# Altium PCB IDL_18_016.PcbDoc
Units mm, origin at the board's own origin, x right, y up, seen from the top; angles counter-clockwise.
Board outline 60 x 33 mm, 2 copper layers (Top Layer, Bottom Layer), stack 1.568 mm thick; 47 components, 22 nets, 136 pads, 21 vias.
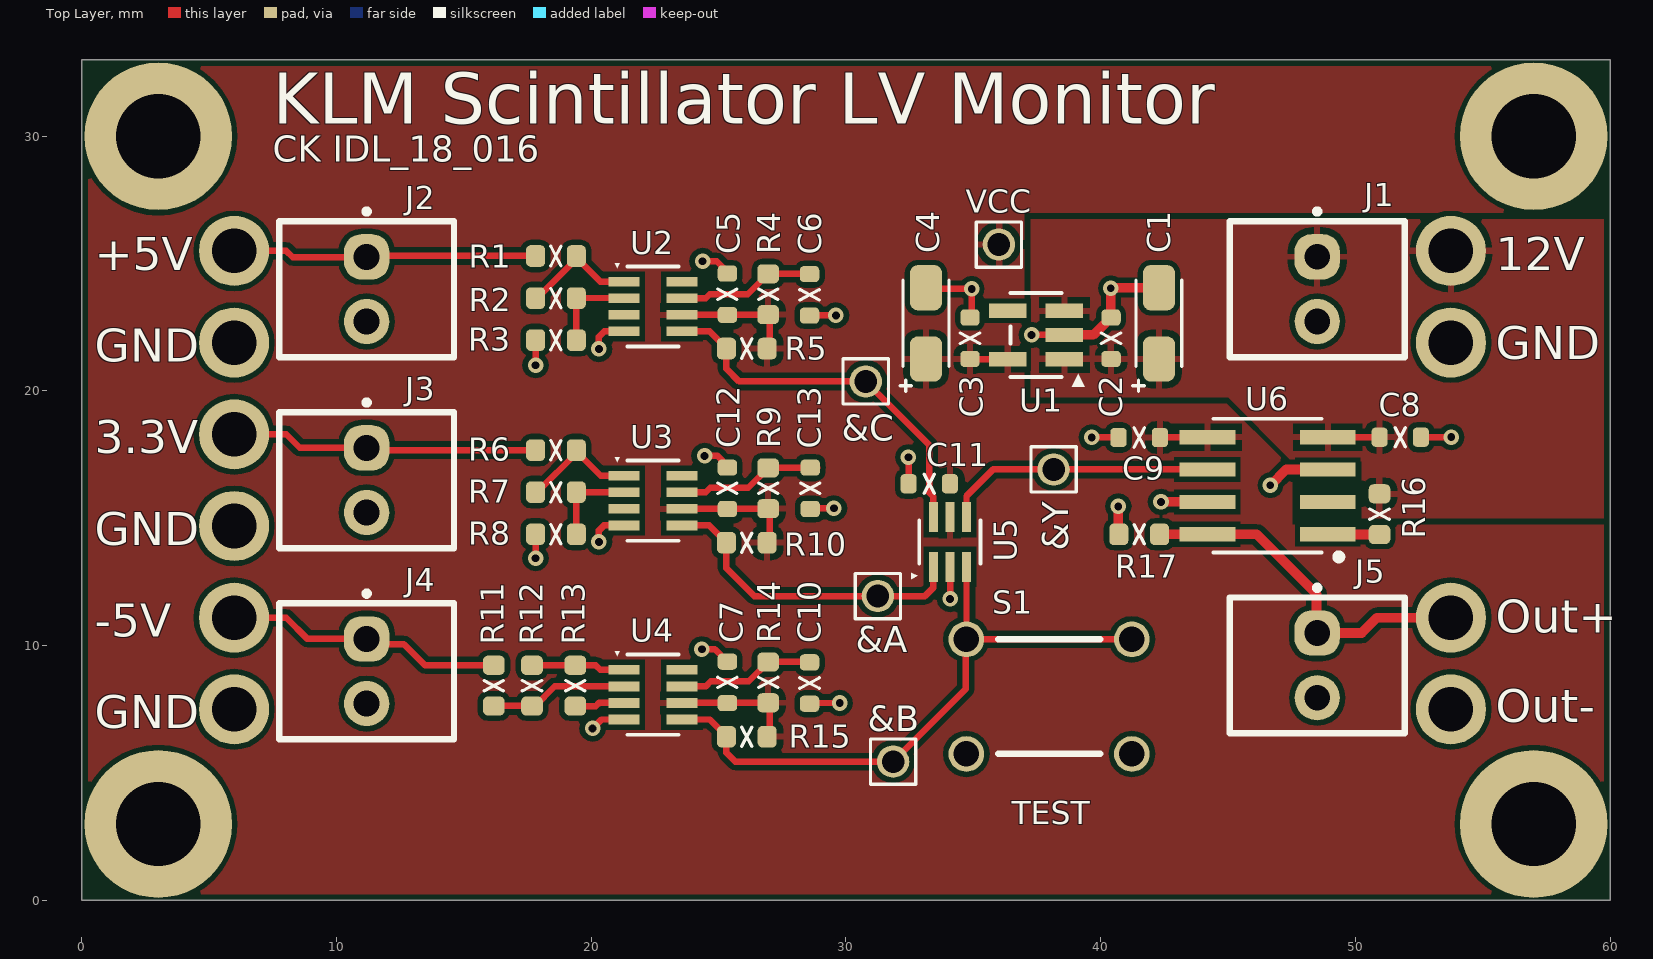
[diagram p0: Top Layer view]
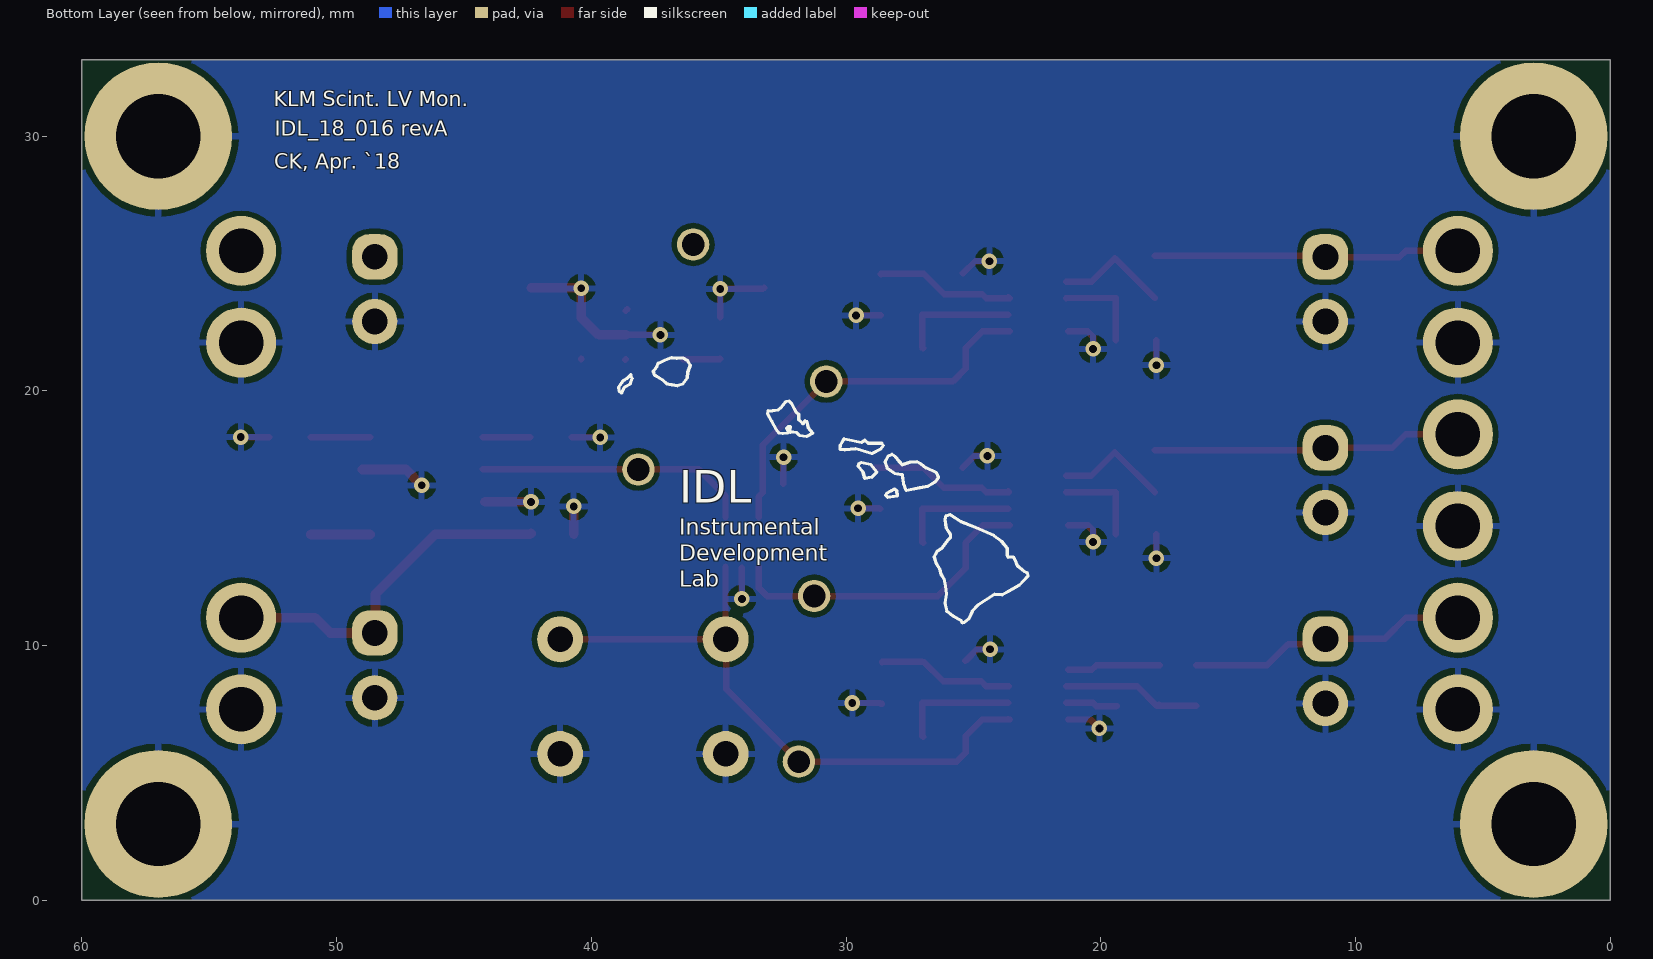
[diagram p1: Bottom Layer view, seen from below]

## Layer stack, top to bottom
Top Solder: solder mask 0.0102, Solder Resist, Dk 3.5
Top Layer: signal copper 0.0348
Dielectric 1: core 1.4986, FR-4, Dk 4.2
Bottom Layer: signal copper 0.0348
Bottom Solder: solder mask 0.0102, Solder Resist, Dk 3.5

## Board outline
0,0 0,33 60,33 60,0

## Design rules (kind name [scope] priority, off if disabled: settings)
Clearance [All] p1: gap=0.203 ignorepadtopadclearanceinfootprint=FALSE
HoleSize [All] p1: absolutevalues=TRUE maxlimit=5.5 minlimit=0.025 maxpercent=80.000 minpercent=20.000
MinimumSolderMaskSliver [All] p1: minsoldermaskwidth=0.102
PolygonConnect [All] p1: connectstyle=Relief reliefconductorwidth=0.254 reliefentries=4 polygonreliefangle="90 Angle" airgapwidth=0.254
RoutingVias [All] p1: holewidth=0.305 width=0.61 viastyle="Through Hole" minholewidth=0.305 minwidth=0.61 maxholewidth=0.762 maxwidth=1.524
SilkToSilkClearance [All] p1: silktosilkclearance=0.127
SilkToSolderMaskClearance [IsPad] p1: minsilkscreentomaskgap=0.127 clearancetoexposedcopper=TRUE
SolderMaskExpansion [All] p1: expansion=0.051
Width [All] p1: maxlimit=1.016 minlimit=0.254 preferedwidth=0.254
26 further rules are at their usual default settings.

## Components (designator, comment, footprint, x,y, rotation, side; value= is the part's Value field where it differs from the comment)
&A "testpoint" testpoint 31.25,11.95 r0 top
&B "testpoint" testpoint 31.85,5.45 r270 top
&C "testpoint" testpoint 30.775,20.375 r0 top
&Y "testpoint" testpoint 38.151,16.92 r0 top (schematic designator &out)
C1 "1uF" CTC-A3216-18 42.286,22.657 r90 top
C2 "100nF" CC0603RF1R 40.406,22.073 r270 top
C3 "100nF" CC0603RF1R 34.869,22.073 r270 top
C4 "2.2uF" CTC-A3216-18 33.142,22.657 r90 top
C5 "100nF" CC0603RF1R 25.344,23.8 r270 top
C6 "Do Not Install" CC0603RF1R 28.57,23.774 r90 top
C7 "100nF" CC0603RF1R 25.344,8.56 r270 top
C8 "100nF" CC0603RF1R 51.76,18.187 r180 top
C9 "100nF" CC0603RF1R 41.511,18.174 r180 top
C10 "Do Not Install" CC0603RF1R 28.57,8.534 r90 top
C11 "100nF" CC0603RF1R 33.269,16.358 r0 top
C12 "100nF" CC0603RF1R 25.344,16.18 r270 top
C13 "Do Not Install" CC0603RF1R 28.595,16.18 r90 top
J1 "Molex 22-23-2021" 32_MMBX-50-0-4 48.5,24 r270 top
J2 "Molex 22-23-2021" 32_MMBX-50-0-4 11.182,23.997 r270 top
J3 "Molex 22-23-2021" 32_MMBX-50-0-4 11.182,16.497 r270 top (schematic designator J4)
J4 "Molex 22-23-2021" 32_MMBX-50-0-4 11.182,8.997 r270 top (schematic designator J3)
J5 "Molex 22-23-2021" 32_MMBX-50-0-4 48.5,9.225 r270 top
R1 "100k" RC0603N1R 18.613,25.298 r180 top (schematic designator R2)
R2 "2.61k" RC0603N1R 18.613,23.647 r180 top (schematic designator R3)
R3 "10k" RC0603N1R 18.613,21.996 r0 top (schematic designator R5)
R4 "0" RC0603N1R 26.944,23.8 r270 top (schematic designator R1)
R5 "100k" RC0603N1R 26.106,21.666 r0 top (schematic designator R4)
R6 "61.9k" RC0603N1R 18.613,17.678 r180 top (schematic designator R14)
R7 "2.61k" RC0603N1R 18.613,16.027 r180 top (schematic designator R15)
R8 "10k" RC0603N1R 18.613,14.376 r0 top (schematic designator R17)
R9 "0" RC0603N1R 26.944,16.18 r270 top (schematic designator R13)
R10 "100k" RC0603N1R 26.106,14.046 r0 top (schematic designator R16)
R11 "121k" RC0603N1R 16.174,8.433 r90 top (schematic designator R7)
R12 "2.1k" RC0603N1R 17.673,8.433 r90 top (schematic designator R8)
R13 "10k" RC0603N1R 19.375,8.433 r270 top (schematic designator R12)
R14 "0" RC0603N1R 26.944,8.56 r270 top (schematic designator R6)
R15 "100k" RC0603N1R 26.106,6.426 r0 top (schematic designator R10)
R16 "3.74k" RC0603N1R 50.947,15.164 r270 top (schematic designator R9)
R17 "4.99k" RC0603N1R 41.511,14.374 r0 top (schematic designator R11)
S1 "B3F-1052" B3F-1052 37.975,8 r180 top
U1 "TPS76033DBVR" DBV5 37.46,22.2 r180 top value=Value
U2 "LTC2909ITS8-3.3#TR" TSOT-23_TS8 22.423,23.317 r0 top value=Value
U3 "LTC2909ITS8-3.3#TR" TSOT-23_TS8 22.423,15.697 r0 top value=Value (schematic designator U4)
U4 "LTC2909ITS8-3.3#TR" TSOT-23_TS8 22.423,8.077 r0 top value=Value (schematic designator U3)
U5 "SN74LVC1G11DCKR" DCK6 34.081,14.072 r90 top value=Value
U6 "ADG417BRZ" R_8 46.553,16.281 r180 top value=Value
VCC "testpoint" testpoint 36,25.75 r0 top

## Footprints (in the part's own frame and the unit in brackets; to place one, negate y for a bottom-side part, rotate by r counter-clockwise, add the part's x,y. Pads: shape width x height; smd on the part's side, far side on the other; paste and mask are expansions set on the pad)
32_MMBX-50-0-4 [mil] "MMBX adapter 8mm"
  rrect75% 70x70 hole 40: 1(-50,0)
  round 70 hole 40: 2(50,0)
  silkscreen extent -123,-135 105,135, body extent -97,-125 97,125, height 420
B3F-1052 [mm]
  round 1.4 / inner round 1.524 / far side round 1.8 hole 1 mask+0.051: 1(3.25,-2.25) 2(-3.25,-2.25) 3(3.25,2.25) 4(-3.25,2.25)
  silkscreen extent -2,-2.25 2,2.25, body extent -3,-3 3,3, height 7.3
CC0603RF1R [mil] "Chip capacitor 0603 RF pad ROUNDED PAD"
  rrect50% 25x30 smd: 1(-32,0) 2(32,0)
  silkscreen extent -8,-15 8,15, body extent -30,-15 30,15, height 28
CTC-A3216-18 [mil] "Capacitor tantal chip A - 3216, H=1.6mm"
  rrect50% 70x50 smd: 1(-55,0) 2(55,0)
  silkscreen extent -105,-35 67,40, body extent -68,-31 68,31, height 63
DBV5 [mil]
  rect 58x22 smd paste+0 mask+2: 1(-44,37.4) 2(-44,0) 3(-44,-37.4) 4(44,-37.4) 5(44,37.4)
  silkscreen extent -75,-65 40,80, body extent -59,-60 59,60, height 57
DCK6 [mil]
  rect 46x14 smd paste+0 mask+2: 1(-38.5,25.59) 2(-38.5,0) 3(-38.5,-25.59) 4(38.5,-25.59) 5(38.5,0) 6(38.5,25.59)
  silkscreen extent -58,-48 33,60, body extent -45,-43 50,43, height 43
R_8 [mil]
  rect 86x22 smd paste+0 mask+0: 1(-93,75) 2(-93,25) 3(-93,-25) 4(-93,-75) 5(93,-75) 6(93,-25) 7(93,25) 8(93,75)
  silkscreen extent -115,-104 84,115, body extent -122,-98 122,99, height 69
RC0603N1R [mm] "Chip resistor 0603 ROUNDED PAD"
  rrect50% 0.75x0.85 smd: 1(-0.8,0) 2(0.8,0)
  silkscreen extent -0.2,-0.38 0.2,0.38, body extent -0.8,-0.4 0.8,0.4, height 0.46
testpoint [mil]
  round 50 hole 35 mask+4: 1(0,0)
  silkscreen extent -35,-35 35,35
TSOT-23_TS8 [mil]
  rect 48x15 smd paste+0 mask+2: 1(-45,38.39) 2(-45,12.8) 3(-45,-12.8) 4(-45,-38.39) 5(45,-38.39) 6(45,-12.8) 7(45,12.8) 8(45,38.39)
  silkscreen extent -59,-62 40,67, body extent -55,-57 55,57, height 39

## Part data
C1: library part CAPT3216_1U_35V, "Capacitor tantal smd 3216-18 35V 7.5Resr", Manufacturer=KEMET, Manufacturer No=T491A105K035AT, Package="Tant SMD A 3216-18", Supplier Part Number 1=399-8265-1-ND, Voltage rating=35V
C2 C3: library part CAPCC0603_1_100N_100VX7R, "Capacitor chip ceramic 0603 100V X7R", Manufacturer=Murata, Manufacturer No=GRM188R72A104KA35D, Package="Cap Chip 0603", Supplier Part Number 1=490-3285-1-ND, Voltage rating=100V
C4: library part CAPT3216_2.2U_16V, "Capacitor tantal smd 3216-18 16V 6.5Resr", Manufacturer=AVX, Manufacturer No=TAJA225K016R, Package="Tant SMD A 3216-18", Supplier Part Number 1=478-2353-1-ND, Voltage rating=16V
C5 C6 C7 C10 C11 C12 C13: library part CAPCC0603_1_100N_50VX7R, "Capacitor chip ceramic 0603 50V X7R", Manufacturer=Murata, Manufacturer No=GRM188R71H104KA93D, Package="Cap Chip 0603", Supplier Part Number 1=81-GRM39X104K50D
C8 C9: library part CAPCC0603_1_100N_50VX7R, "Capacitor chip ceramic 0603 50V X7R", Manufacturer=Murata, Manufacturer No=GRM188R71H104KA93D, Package="Cap Chip 0603", Supplier Part Number 1=81-GRM39X104K50D, Voltage rating=50V
J1 J2 J3 J4 J5: "KK 100 Header Assy"
R1 R2 R3 R5 R6 R7 R8 R10 R11 R12 R13 R15: library part PR_RES0603-1_100k-0.1%25PPM, "Chip Resistor 0603 100mW 0.1% 25ppm", Manufacturer=Panasonic, Manufacturer No=ERA-3AEB104V, Package="Res Chip 0603", Supplier Part Number 1=P100KDBCT-ND
R4 R9 R14 R16 R17: library part PR_RES0603-1_4.99k-0.1%25PPM, "Chip Resistor 0603 100mW 0.1% 25ppm", Manufacturer=Panasonic, Manufacturer No=ERA-3AEB4991V, Package="Res Chip 0603", Supplier Part Number 1=667-ERA-3AEB4991V
S1: "Switch Tactile 0.5A 24V SW405-ND"
U1 U5: "Imported", Manufacturer="Texas Instruments"
U2 U3 U4: "IC MONITOR PREC 3.3V TSOT23-8 LTC2909ITS8-3.3#TRMPBFCT-ND", Manufacturer_Part_Number=LTC2909ITS8-5#TRMPBF
U6: "Analog Switch"

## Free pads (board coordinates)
  round 2.75 hole 1.75: 3(5.975,7.5) 3(5.975,11.1) 3(5.975,14.7) 3(5.975,18.3) 3(5.975,21.9) 3(5.975,25.5) 3(53.75,7.5) 3(53.75,11.1) 3(53.75,21.9) 3(53.75,25.5)
  round 5.8 hole 3.3: 4(3,3) 4(3,30) 4(57,3) 4(57,30)

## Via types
v1: diameter 0.61, hole 0.305, Top Layer to Bottom Layer, 21 vias

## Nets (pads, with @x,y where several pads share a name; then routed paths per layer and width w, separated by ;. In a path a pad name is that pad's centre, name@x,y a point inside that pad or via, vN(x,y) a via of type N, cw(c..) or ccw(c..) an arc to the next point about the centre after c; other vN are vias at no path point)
3p3V: J3.1 pad.3@5.975,18.3 R6.2 | length 12.2
  Top Layer w0.254: pad.3@5.975,18.3 8.025,18.3 8.558,17.767 J3.1@11.102,17.767 ; J3.1 J3.1@11.102,17.767 ; R6.2@17.881,17.681 11.188,17.681 J3.1@11.102,17.767
5V: J2.1 pad.3@5.975,25.5 R1.2 | length 12
  Top Layer w0.254: pad.3@5.975,25.5 8.025,25.5 8.275,25.25 11.137,25.25 11.188,25.301 R1.2@17.881,25.301
12V: C1.1 C2.2 C8.2 J1.1 pad.3@53.75,25.5 R16.1 U1.1 U1.3 U6.4 | length 2.5
  Top Layer w0.254: U1.3@38.595,23.203 U1.3@38.646,23.152 ; U1.1@38.646,21.252 U1.1@38.671,21.227 ; C2.2@40.388,21.252 C2.2@40.398,21.263 ; U6.4@48.679,18.189 C8.2@51.015,18.189
-5V: J4.1 pad.3@5.975,11.1 R11.2 | length 11.1
  Top Layer w0.254: pad.3@5.975,11.1 8.025,11.1 8.858,10.267 J4.1 ; J4.1@11.089,10.16 11.188,10.061 12.646,10.061 13.472,9.236 R11.2@16.243,9.236
GND: C1.2 C2.1 C3.1 C4.2 C5.1 C6.1 C7.1 C8.1 C9.2 C10.1 C11.1 C12.1 C13.1 J1.2 J2.2 J3.2 J4.2 J5.2 pad.3@5.975,7.5 pad.3@5.975,14.7 pad.3@5.975,21.9 pad.3@53.75,7.5 pad.3@53.75,21.9 pad.4 R3.1 R8.1 R17.1 S1.3 S1.4 U1.2 U2.4 U3.4 U4.4 U5.2 U6.3 U6.7 | length 32.2
  Top Layer w0.254: v1(17.813,13.438) R8.1 ; v1(17.813,21.013) R3.1 ; v1(20.05,6.75) 20.402,7.102 U4.4 ; v1(20.301,14.075) 20.301,14.526 20.497,14.722 U3.4 ; v1(20.3,21.65) 20.3,22.125 20.517,22.342 U2.4 ; v1(24.345,9.858) 24.853,9.858 C7.1@25.311,9.401 ; v1(24.371,25.098) 24.93,25.098 C5.1@25.412,24.615 ; v1(24.447,17.453) 24.955,17.453 C12.1@25.412,16.995 ; C10.1@28.587,7.724 28.638,7.724 28.664,7.75 v1(29.75,7.75) ; C6.1@28.638,22.964 v1@29.578,22.964 ; C13.1@28.663,15.37 28.686,15.392 v1(29.525,15.392) ; v1(32.45,17.4) 32.456,17.394 C11.1 ; C4.2@33.21,24.057 33.261,24.006 v1(34.937,24.006) C3.1@34.937,22.888 ; v1(34.088,11.835) U5.2@34.088,13.059 ; v1(37.287,22.2) U1.2@38.557,22.2 ; v1(39.649,18.177) C9.2@40.767,18.177 ; v1(40.398,24.031) v1@40.424,24.057 ; C8.1@52.641,18.19 v1(53.76,18.19)
  Top Layer w0.381: U1.2@38.646,22.202 39.712,22.202 40.398,22.888 v1(40.398,24.031) ; v1@40.424,24.057 C1.2@42.354,24.057 ; R17.1@40.691,14.374 v1(40.691,15.469) ; v1(42.367,15.646) U6.7@44.171,15.646 ; v1(46.66,16.297) 47.282,16.919 U6.3@48.983,16.919
  other v1: 29.603,22.964
Net&A_1: &A.1 R10.1 U3.5 U5.1 | length 12.6
  Top Layer w0.254: U3.5 24.63,14.722 R10.1 25.306,13.044 26.4,11.95 &A.1 33.1,11.95 33.431,12.281 U5.1
Net&B_1: &B.1 R15.1 S1.1 S1.2 U4.5 U5.3 | length 24.7
  Top Layer w0.254: U4.5 U4.5@23.634,7.102 ; U4.5@23.634,7.105 U4.5@23.634,7.102 ; U5.3 34.731,10.256 S1.1 ; S1.2 S1.1 ; U4.5@23.634,7.102 24.648,7.102 25.306,6.444 R15.1 25.306,5.799 25.655,5.45 &B.1 34.7,8.3 34.7,10.225 S1.1
Net&C_1: &C.1 R5.1 U2.5 U5.6 | length 14.9
  Top Layer w0.254: U2.5 24.642,22.342 25.306,21.679 R5.1 25.306,20.869 25.8,20.375 &C.1 33.275,17.875 33.275,16 33.431,15.844 U5.6
Net&Y_1: &Y.1 U5.4 U6.6 | length 10.8
  Top Layer w0.254: U5.4 34.731,15.875 35.775,16.919 &Y.1 U6.6@44.259,16.919
NetC6_2: C6.2 R4.1 U2.7 | length 5.4
  Top Layer w0.254: U2.7 24.492,23.642 24.65,23.8 26.144,23.8 R4.1 ; U2.7@23.634,23.645 U2.7@23.634,23.688 ; R4.1@27.012,24.603 28.625,24.603 C6.2@28.638,24.59
NetC10_2: C10.2 R14.1 U4.7 | length 5.3
  Top Layer w0.254: U4.7@23.61,8.402 24.492,8.402 24.69,8.6 26.184,8.6 R14.1 ; R14.1@27.012,9.363 28.575,9.363 C10.2@28.587,9.35
NetC13_2: C13.2 R9.1 U3.7 | length 5.6
  Top Layer w0.254: U3.7@23.611,16.022 24.492,16.022 24.67,16.2 26.164,16.2 R9.1 ; U3.7@23.634,16.025 U3.7@23.634,16.068 ; R9.1@27.012,16.983 28.854,16.983 C13.2@28.867,16.995
NetJ5_1: J5.1 pad.3@53.75,11.1 R17.2 U6.8 | length 14.5
  Top Layer w0.381: R17.2@42.367,14.405 42.392,14.379 U6.8@44.259,14.379 ; U6.8 46.124,14.376 48.475,12.025 48.475,10.52 J5.1 50.245,10.495 50.85,11.1 pad.3@53.75,11.1 ; pad.3@53.75,10.5 pad.3@54,10.5
NetR1_1: R1.1 R2.2 U2.1 | length 4.5
  Top Layer w0.254: R2.2@17.881,23.65 19.44,25.209 20.355,24.295 U2.1@21.348,24.295
NetR2_1: R2.1 R3.2 U2.2 | length 3.6
  Top Layer w0.254: R3.2 R2.1 ; R2.1@19.413,23.65 21.343,23.65 U2.2@21.348,23.645
NetR6_1: R6.1 R7.2 U3.1 | length 4.5
  Top Layer w0.254: R7.2@17.881,16.03 19.45,17.599 20.375,16.675 U3.1@21.348,16.675
NetR7_1: R7.1 R8.2 U3.2 | length 3.6
  Top Layer w0.254: R8.2 R7.1 ; R7.1@19.413,16.03 21.343,16.03 U3.2@21.348,16.025
NetR11_1: R11.1 R12.1 U4.2 | length 5.4
  Top Layer w0.254: R11.1@16.243,7.636 17.665,7.636 R12.1@17.703,7.674 ; R12.1@17.741,7.636 17.796,7.636 18.565,8.405 U4.2@21.348,8.405
NetR12_2: R12.2 R13.1 U4.1 | length 3.7
  Top Layer w0.254: R12.2 R13.1 19.383,9.225 20.179,9.225 20.352,9.052 U4.1
NetR13_2: R13.2 U4.3 | length 2
  Top Layer w0.254: R13.2 19.383,7.625 20.175,7.625 20.302,7.752 U4.3 ; U4.3@21.341,7.763 U4.3@21.348,7.755
NetR16_2: R16.2 U6.1 | length 2.3
  Top Layer w0.254: U6.1@48.983,14.379 U6.1@48.996,14.367
  Top Layer w0.381: U6.1@48.691,14.367 R16.2@51.015,14.367
VCC: C3.2 C4.1 C5.2 C7.2 C9.1 C11.2 C12.2 R4.2 R5.2 R9.2 R10.2 R14.2 R15.2 U1.5 U2.6 U3.6 U4.6 U5.5 U6.5 VCC.1 | length 17.5
  Top Layer w0.254: U4.6@23.634,7.755 25.412,7.755 27.005,7.755 27.012,7.763 27.012,6.467 R15.2@26.974,6.429 ; U3.6@23.634,15.375 25.412,15.375 27.005,15.375 27.012,15.383 27.012,14.087 R10.2@26.974,14.049 ; U2.6@23.634,22.995 25.412,22.995 27.005,22.995 27.012,23.003 27.012,21.707 R5.2@26.974,21.669 ; C3.2@34.937,21.263 34.947,21.252 U1.5@36.41,21.252 ; C9.1@42.393,18.177 42.405,18.189 U6.5@44.259,18.189
pads on no net: U1.4 U2.3 U2.8 U3.3 U3.8 U4.8 U6.2

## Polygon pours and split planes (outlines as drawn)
VCC on Top Layer "Top Layer-VCC" (solid, pour order 10): 59.75,14.75 47.521,14.75 47.521,16.979 45,19.5 37,19.5 37,27 59.75,27 59.75,32.75 6.345,32.75 0.25,32.75 0.25,26.606 0.25,6.106 0.25,0.25 6.25,0.25 53.845,0.25 59.75,0.25 59.75,6.106
12V on Top Layer "Top Layer-12V" (solid, pour order 2): 37.25,19.75 37.25,26.75 51.25,26.75 59.75,26.75 59.75,20.25 59.75,15 50.25,15 50.25,17.25 47.5,17.25 45,19.75
no net on Top Layer "Top Layer-No Net" (solid, pour order 12): 38,8.5
no net on Top Layer "Top Layer-No Net 1" (solid, pour order 6): 41.25,32.75
no net on Top Layer "Top Layer-No Net 2" (solid, pour order 4): 41.25,28
GND on Bottom Layer "Bottom Layer-GND" (solid, pour order 8): 60,33 60,0 0,0 0,33

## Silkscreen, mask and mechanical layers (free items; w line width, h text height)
Top Overlay:
  text "KLM Scintillator LV Monitor" at 7.5,30.5 h2
  text "CK IDL_18_016" at 7.5,29 h1.02
  text "+5V" at 0.5,24.75 h1.3
  text "12V" at 55.5,24.75 h1.3
  text "GND" at 55.5,21.25 h1.3
  text "GND" at 0.5,21.15 h1.3
  text "3.3V" at 0.5,17.55 h1.3
  text "GND" at 0.5,13.95 h1.3
  text "Out+" at 55.5,10.5 h1.3
  text "-5V" at 0.5,10.35 h1.3
  text "Out-" at 55.5,7 h1.3
  text "GND" at 0.5,6.75 h1.3
  text "TEST" at 36.5,3 h0.9
Bottom Overlay:
  drawing of 160 lines, arcs and shapes, not listed
  text "KLM Scint. LV Mon." at 52.47,30.988 h1
  text "IDL_18_016 revA" at 52.435,29.825 h1
  text "CK, Apr. `18" at 52.442,28.525 h1
  text "IDL" at 36.544,15.617 h1.27
  text "Instrumental" at 36.544,14.347 h0.64
  text "Development" at 36.544,13.331 h0.64
  text "Lab" at 36.544,12.315 h0.64
Mechanical 2:
  lines w0.099: -88.786,-134.878 391.272,-134.878 391.272,213.925 -88.786,213.925 -88.786,-134.878 ; -86.239,-132.346 388.725,-132.346 388.725,211.393 -86.239,211.393 -86.239,-132.346
  lines w0.1: 218.808,-132.346 218.808,-114.307 388.725,-114.307 ; 218.808,-123.431 388.734,-123.431 ; 218.808,-120.403 341.236,-120.403 ; 218.808,-117.355 341.236,-117.355 ; 257.035,-123.431 257.035,-114.307 ; 282.435,-123.431 282.435,-114.307 ; 322.821,-123.431 322.821,-114.307 ; 341.236,-132.346 341.236,-114.307 ; 341.236,-118.879 388.725,-118.879
  text "Designer:" at 219.443,-116.593 h2.54
  text ".Designer" at 233.794,-116.72 h2.54
  text "Revision:" at 257.67,-116.72 h2.54
  text ".Version" at 271.894,-116.72 h2.54
  text "File:" at 283.07,-116.72 h2.54
  text ".Pcb_File_Name_No_Path" at 288.15,-116.72 h2.54
  text "Sheet  1 of  1" at 323.583,-116.72 h2.54
  text "Code:" at 341.871,-117.863 h2.54
  text "Drawn By:" at 219.443,-119.641 h2.54
  text ".Drawn_By" at 233.794,-119.641 h2.54
  text "Modif. Date:" at 257.67,-119.768 h2.54
  text "Date" at 270.497,-119.768 h2.54
  text "Variant:" at 283.07,-119.768 h2.54
  text ".VariantName" at 292.341,-119.768 h2.54
  text "ID:" at 341.998,-122.435 h2.54
  text "Approved By:" at 219.443,-122.689 h2.54
  text ".Approved_By" at 233.794,-122.689 h2.54
  text "Print Date:" at 257.67,-122.816 h2.54
  text ".Print_Date" at 270.497,-122.816 h2.54
  text "Signature:" at 283.07,-122.816 h2.54
  text "Size:  A3 H" at 323.583,-122.816 h2.54
  text "Title:" at 219.443,-125.991 h2.54
  text "University of Hawaii at Manoa" at 342.034,-126.201 h2.54
  text "High Energy Physics Group" at 342.034,-128.701 h2.54
  text ".Printout_Name" at 225.158,-129.547 h4.06
  text "Instrumentation Development Laboratory" at 342.034,-131.301 h2.54
Mechanical 3:
  lines w0.099: -10.052,-134.873 391.265,-134.873 391.265,156.716 ; -7.506,-132.341 388.719,-132.341 388.719,154.184 ; -88.786,-134.878 391.272,-134.878 391.272,213.925 -88.786,213.925 -88.786,-134.878 ; -86.239,-132.346 388.725,-132.346 388.725,211.393 -86.239,211.393 -86.239,-132.346
  lines w0.1: -86.255,-123.426 83.671,-123.426 ; -86.246,-118.874 -38.757,-118.874 ; -86.246,-114.302 83.671,-114.302 83.671,-132.341 ; -38.757,-132.341 -38.757,-114.302 ; -38.757,-120.398 83.671,-120.398 ; -38.757,-117.35 83.671,-117.35 ; -20.342,-123.426 -20.342,-114.302 ; 20.044,-123.426 20.044,-114.302 ; 45.444,-123.426 45.444,-114.302
  text "Designer:" at 83.036,-116.588 h2.54
  text "Sheet  1 of  1" at -21.104,-116.715 h2.54
  text ".Pcb_File_Name_No_Path" at 14.329,-116.715 h2.54
  text "File:" at 19.409,-116.715 h2.54
  text ".Version" at 30.585,-116.715 h2.54
  text "Revision:" at 44.809,-116.715 h2.54
  text ".Designer" at 68.685,-116.715 h2.54
  text "Code:" at -39.392,-117.858 h2.54
  text ".Drawn_By" at 68.685,-119.636 h2.54
  text "Drawn By:" at 83.036,-119.636 h2.54
  text ".VariantName" at 10.138,-119.763 h2.54
  text "Variant:" at 19.409,-119.763 h2.54
  text "Date" at 31.982,-119.763 h2.54
  text "Modif. Date:" at 44.809,-119.763 h2.54
  text "ID:" at -39.519,-122.43 h2.54
  text ".Approved_By" at 68.685,-122.684 h2.54
  text "Approved By:" at 83.036,-122.684 h2.54
  text "Size:  A3 H" at -21.104,-122.811 h2.54
  text "Signature:" at 19.409,-122.811 h2.54
  text ".Print_Date" at 31.982,-122.811 h2.54
  text "Print Date:" at 44.809,-122.811 h2.54
  text "Title:" at 83.036,-125.986 h2.54
  text "University of Hawaii at Manoa" at -39.604,-126.301 h2.54
  text "High Energy Physics Group" at -39.604,-128.801 h2.54
  text ".Printout_Name" at 77.321,-129.542 h4.06
  text "Instrumentation Development Laboratory" at -39.604,-131.401 h2.54
Board Outline:
  the board outline again, w0.254
Drill Drawing:
  drawing of 241 lines, arcs and shapes, not listed
  text "Notes:" at 89.037,128.143 h3.3
  text "1. Board shall be fabricated - performace class II as per IPC-6011 and IPC6012" at 89.032,125.144 h2.54
  text "2. PCB manufacturer logo, P/N, revision and/or date code of manufacturing" at 89.03,121.753 h2.54
  text "shall be printed in top solder mask (not over pcb traces, allowed over copper plane)." at 91.577,118.336 h2.54
  text "The date code shall be in the format: \"WWYY\" where WW=week and YY= year, max height 0.15 inches" at 91.577,114.92 h2.54
  text "3. Silkscreen printed on both sides" at 89.032,111.476 h2.54
  text "4. Material: high temperature FR4 class epoxy glass rated UL94V-0. UL symbol and rating shall be marked farside" at 89.032,108.086 h2.54
  text "35um copper for external layers and 18um for all internal layers" at 91.578,104.669 h2.54
  text "Must be RoHS compliant and survive a lead-free assembly max reflow of 260 deg C (5 passes)" at 91.577,101.252 h2.54
  text "Td rating: >340 deg C" at 92.847,97.835 h2.54
  text "Tg = 150 deg C (min)" at 92.95,94.419 h2.54
  text "5. Solder mask: SMOBC per IPC-SM-840C, class T must be Rohs compliant, 0.001\" max measured over bare copper plating," at 89.032,91.002 h2.54
  text "must clear all lands as indicated on gerber solder mask layers, color= GREEN" at 91.577,87.585 h2.54
  text "6. Finish: electro-less nickel immersion gold (ENIG), 0.05-0.125um Au over 3-6um Ni - over bare copper only" at 89.032,84.168 h2.54
  text "7. Solderability test: Category 2 of J-STD-003" at 89.032,80.751 h2.54
  text "8. Finished boards shall not have nicks, scratches, voids, exposed copper, poor plating or misdrilled holes" at 89.032,77.335 h2.54
  text "9. All holes sizes are after plating" at 89.032,73.918 h2.54
  text "10. PCB manufacturer may add copper thieving as needed to improve manufacturability," at 87.767,70.501 h2.54
  text "thieving to be 0.030\" round pads at 0.050\" spacing." at 91.577,67.084 h2.54
  text "Thieving will have a minimum of 0.100\" clearance from existing copper and should not be placed under surface mounted devices" at 91.577,63.667 h2.54
  text "11. PCB manufacturer may use tear drops to improve annular rings as long as DRC rules are followed" at 87.894,60.25 h2.54
  text "12. All finished boards are to be 100% electrically tested" at 88,56.834 h2.54
  text "13. Gerber file GM5 shows board outline (milling line)" at 88,53.417 h2.54
  text "14. Table 1 shows Layer stack details" at 88,50 h2.54
  text "Additional notes:" at 88,43 h3.3
  text "A1. Finished board thickness = 62.5mils +/- 10%; measured over top/bottom copper and solder mask" at 88,39 h2.54
  text "Table 1: Layer Stack Details for IDL_18_016 Rev.A" at 87,31 h2.5
  text "Layer" at 88.973,27.144 h1.52
  text "Name" at 99.384,27.144 h1.52
  text "Material" at 123,27.144 h1.52
  text "Thickness" at 144.838,27.144 h1.52
  text "Constant" at 161.344,27.144 h1.52
  text "Board Layer Stack" at 175.818,27.144 h1.52
  text "1" at 88.973,24.096 h1.52
  text "Top Overlay" at 99.384,24.096 h1.52
  text "2" at 88.973,21.048 h1.52
  text "Top Solder" at 99.384,21.048 h1.52
  text "Solder Resist" at 123,21.048 h1.52
  text "0.40mil" at 144.838,21.048 h1.52
  text "3.5" at 161.344,21.048 h1.52
  text "3" at 88.973,18 h1.52
  text "Top Layer" at 99.384,18 h1.52
  text "Copper" at 123,18 h1.52
  text "1.37mil" at 144.838,18 h1.52
  text "4" at 88.973,14.952 h1.52
  text "Dielectric 1" at 99.384,14.952 h1.52
  text "FR-4" at 123,14.952 h1.52
  text "59.00mil" at 144.838,14.952 h1.52
  text "4.2" at 161.344,14.952 h1.52
  text "5" at 88.973,11.904 h1.52
  text "Bottom Layer" at 99.384,11.904 h1.52
  text "Copper" at 123,11.904 h1.52
  text "1.37mil" at 144.838,11.904 h1.52
  text "6" at 88.973,8.856 h1.52
  text "Bottom Solder" at 99.384,8.856 h1.52
  text "Solder Resist" at 123,8.856 h1.52
  text "0.40mil" at 144.838,8.856 h1.52
  text "3.5" at 161.344,8.856 h1.52
  text "7" at 88.973,5.808 h1.52
  text "Bottom Overlay" at 99.384,5.808 h1.52
  text "Table 2: NC Drill Details for IDL_18_016 Rev.A" at 87,-4 h2.5
  text "Symbol" at 90,-8 h1.83
  text "Count" at 102.849,-8 h1.83
  text "Hole Size" at 116.562,-8 h1.83
  text "Plated" at 142.716,-8 h1.83
  text "Hole Type" at 155.565,-8 h1.83
  text "21" at 102.849,-11.81 h1.52
  text "0.31mm (12.0mil)" at 116.562,-11.81 h1.52
  text "PTH" at 142.716,-11.81 h1.52
  text "Round" at 155.565,-11.81 h1.52
  text "5" at 102.849,-15.62 h1.52
  text "0.89mm (35.0mil)" at 116.562,-15.62 h1.52
  text "PTH" at 142.716,-15.62 h1.52
  text "Round" at 155.565,-15.62 h1.52
  text "4" at 102.849,-19.43 h1.52
  text "1.00mm (39.4mil)" at 116.562,-19.43 h1.52
  text "PTH" at 142.716,-19.43 h1.52
  text "Round" at 155.565,-19.43 h1.52
  text "10" at 102.849,-23.24 h1.52
  text "1.02mm (40.0mil)" at 116.562,-23.24 h1.52
  text "PTH" at 142.716,-23.24 h1.52
  text "Round" at 155.565,-23.24 h1.52
  text "10" at 102.849,-27.05 h1.52
  text "1.75mm (68.9mil)" at 116.562,-27.05 h1.52
  text "PTH" at 142.716,-27.05 h1.52
  text "Round" at 155.565,-27.05 h1.52
  text "4" at 102.849,-30.86 h1.52
  text "3.30mm (129.9mil)" at 116.562,-30.86 h1.52
  text "PTH" at 142.716,-30.86 h1.52
  text "Round" at 155.565,-30.86 h1.52
  text "54 Total" at 102.849,-34.67 h1.52

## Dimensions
0,33 to 0,0 on Drill Drawing
0,33 to 60,33 on Drill Drawing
